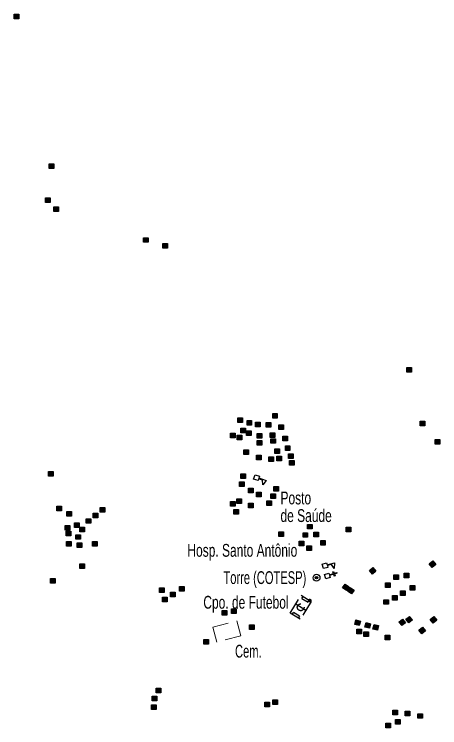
# Model space of a CAD drawing. Extents: x 220.8 to 246.7, y 7287.6 to 7315.8.
# Drawn here: x 230.652 to 233.312, y 7306.736 to 7311.191 of the extents above; entities that cross this region are included whole.
import ezdxf
from ezdxf.enums import TextEntityAlignment as Align

# ---------------------------------------------------------------- set-up
doc = ezdxf.new("R2010")
doc.units = 0
doc.header["$LTSCALE"] = 0.032
doc.header["$PDMODE"] = 32
doc.header["$PDSIZE"] = 0.016
doc.linetypes.add('MEDIUM_DASHED', pattern=[4.5, 3, -1.5])
for name, color, linetype, lineweight in [('14', 7, 'MEDIUM_DASHED', 25), ('2', 7, 'Continuous', 25), ('21', 7, 'MEDIUM_DASHED', 13), ('4', 7, 'Continuous', 25), ('47', 7, 'Continuous', 25), ('6', 7, 'Continuous', 25)]:
    doc.layers.add(name, color=color, linetype=linetype, lineweight=lineweight)
doc.layers.add('61', color=7, linetype='Continuous')

msp = doc.modelspace()

# ---------------------------------------------------------------- hatches: boundary and pattern name
at = {"layer": '2'}
for points in [[(230.6521, 7311.1911), (230.6811, 7311.1911), (230.6811, 7311.1621), (230.6521, 7311.1621)], [(230.8712, 7310.2564), (230.9002, 7310.2564), (230.9002, 7310.2274), (230.8712, 7310.2274)], [(230.8483, 7310.0453), (230.8773, 7310.0453), (230.8773, 7310.0163), (230.8483, 7310.0163)], [(230.8993, 7309.989), (230.9283, 7309.989), (230.9283, 7309.96), (230.8993, 7309.96)], [(231.4593, 7309.7959), (231.4883, 7309.7959), (231.4883, 7309.7669), (231.4593, 7309.7669)], [(231.5801, 7309.7603), (231.6091, 7309.7603), (231.6091, 7309.7313), (231.5801, 7309.7313)], [(233.1068, 7308.9847), (233.1358, 7308.9847), (233.1358, 7308.9557), (233.1068, 7308.9557)], [(232.2676, 7308.697), (232.2966, 7308.697), (232.2966, 7308.668), (232.2676, 7308.668)], [(232.0493, 7308.6713), (232.0783, 7308.6713), (232.0783, 7308.6423), (232.0493, 7308.6423)], [(232.1071, 7308.6542), (232.1361, 7308.6542), (232.1361, 7308.6252), (232.1071, 7308.6252)], [(232.1606, 7308.6435), (232.1896, 7308.6435), (232.1896, 7308.6145), (232.1606, 7308.6145)], [(232.2269, 7308.6414), (232.2559, 7308.6414), (232.2559, 7308.6124), (232.2269, 7308.6124)], [(233.1892, 7308.6494), (233.2182, 7308.6494), (233.2182, 7308.6204), (233.1892, 7308.6204)], [(232.0686, 7308.6071), (232.0976, 7308.6071), (232.0976, 7308.5781), (232.0686, 7308.5781)], [(232.3061, 7308.6264), (232.3351, 7308.6264), (232.3351, 7308.5974), (232.3061, 7308.5974)], [(232.0043, 7308.575), (232.0333, 7308.575), (232.0333, 7308.546), (232.0043, 7308.546)], [(232.045, 7308.5622), (232.074, 7308.5622), (232.074, 7308.5332), (232.045, 7308.5332)], [(232.1049, 7308.59), (232.1339, 7308.59), (232.1339, 7308.561), (232.1049, 7308.561)], [(232.1713, 7308.5729), (232.2003, 7308.5729), (232.2003, 7308.5439), (232.1713, 7308.5439)], [(232.2526, 7308.5772), (232.2816, 7308.5772), (232.2816, 7308.5482), (232.2526, 7308.5482)], [(232.3318, 7308.5558), (232.3608, 7308.5558), (232.3608, 7308.5268), (232.3318, 7308.5268)], [(232.1713, 7308.5301), (232.2003, 7308.5301), (232.2003, 7308.5011), (232.1713, 7308.5011)], [(232.2569, 7308.5408), (232.2859, 7308.5408), (232.2859, 7308.5118), (232.2569, 7308.5118)], [(233.283, 7308.5358), (233.312, 7308.5358), (233.312, 7308.5068), (233.283, 7308.5068)], [(232.0878, 7308.4702), (232.1168, 7308.4702), (232.1168, 7308.4412), (232.0878, 7308.4412)], [(232.2804, 7308.4766), (232.3094, 7308.4766), (232.3094, 7308.4476), (232.2804, 7308.4476)], [(232.3468, 7308.4958), (232.3758, 7308.4958), (232.3758, 7308.4668), (232.3468, 7308.4668)], [(232.167, 7308.4381), (232.196, 7308.4381), (232.196, 7308.4091), (232.167, 7308.4091)], [(232.2441, 7308.4274), (232.2731, 7308.4274), (232.2731, 7308.3984), (232.2441, 7308.3984)], [(232.2933, 7308.4316), (232.3223, 7308.4316), (232.3223, 7308.4026), (232.2933, 7308.4026)], [(232.3661, 7308.4466), (232.3951, 7308.4466), (232.3951, 7308.4176), (232.3661, 7308.4176)], [(232.3725, 7308.4038), (232.4015, 7308.4038), (232.4015, 7308.3748), (232.3725, 7308.3748)], [(230.8672, 7308.3354), (230.8962, 7308.3354), (230.8962, 7308.3064), (230.8672, 7308.3064)], [(232.0686, 7308.3204), (232.0976, 7308.3204), (232.0976, 7308.2914), (232.0686, 7308.2914)], [(232.06, 7308.2711), (232.089, 7308.2711), (232.089, 7308.2421), (232.06, 7308.2421)], [(232.274, 7308.2412), (232.303, 7308.2412), (232.303, 7308.2122), (232.274, 7308.2122)], [(232.1156, 7308.2326), (232.1446, 7308.2326), (232.1446, 7308.2036), (232.1156, 7308.2036)], [(232.167, 7308.2069), (232.196, 7308.2069), (232.196, 7308.1779), (232.167, 7308.1779)], [(232.2569, 7308.1962), (232.2859, 7308.1962), (232.2859, 7308.1672), (232.2569, 7308.1672)], [(232.0043, 7308.1492), (232.0333, 7308.1492), (232.0333, 7308.1202), (232.0043, 7308.1202)], [(232.0428, 7308.1641), (232.0718, 7308.1641), (232.0718, 7308.1351), (232.0428, 7308.1351)], [(232.2312, 7308.1534), (232.2602, 7308.1534), (232.2602, 7308.1244), (232.2312, 7308.1244)], [(230.9176, 7308.1184), (230.9466, 7308.1184), (230.9466, 7308.0894), (230.9176, 7308.0894)], [(231.1886, 7308.1105), (231.2176, 7308.1105), (231.2176, 7308.0815), (231.1886, 7308.0815)], [(232.1156, 7308.1385), (232.1446, 7308.1385), (232.1446, 7308.1095), (232.1156, 7308.1095)], [(230.9806, 7308.0869), (231.0096, 7308.0869), (231.0096, 7308.0579), (230.9806, 7308.0579)], [(231.1461, 7308.0759), (231.1751, 7308.0759), (231.1751, 7308.0469), (231.1461, 7308.0469)], [(232.0257, 7308.0978), (232.0547, 7308.0978), (232.0547, 7308.0688), (232.0257, 7308.0688)], [(231.102, 7308.0412), (231.131, 7308.0412), (231.131, 7308.0122), (231.102, 7308.0122)], [(230.9696, 7307.9986), (230.9986, 7307.9986), (230.9986, 7307.9696), (230.9696, 7307.9696)], [(231.0279, 7308.0144), (231.0569, 7308.0144), (231.0569, 7307.9854), (231.0279, 7307.9854)], [(231.0626, 7307.9876), (231.0916, 7307.9876), (231.0916, 7307.9586), (231.0626, 7307.9586)], [(232.4859, 7308.0058), (232.5149, 7308.0058), (232.5149, 7307.9768), (232.4859, 7307.9768)], [(232.7273, 7307.9875), (232.7563, 7307.9875), (232.7563, 7307.9585), (232.7273, 7307.9585)], [(230.9775, 7307.9624), (231.0065, 7307.9624), (231.0065, 7307.9334), (230.9775, 7307.9334)], [(231.0378, 7307.9413), (231.0668, 7307.9413), (231.0668, 7307.9123), (231.0378, 7307.9123)], [(232.3068, 7307.9599), (232.3358, 7307.9599), (232.3358, 7307.9309), (232.3068, 7307.9309)], [(232.4572, 7307.9538), (232.4862, 7307.9538), (232.4862, 7307.9248), (232.4572, 7307.9248)], [(232.5247, 7307.9568), (232.5537, 7307.9568), (232.5537, 7307.9278), (232.5247, 7307.9278)], [(230.9782, 7307.8979), (231.0072, 7307.8979), (231.0072, 7307.8689), (230.9782, 7307.8689)], [(231.046, 7307.8898), (231.075, 7307.8898), (231.075, 7307.8608), (231.046, 7307.8608)], [(231.1408, 7307.8979), (231.1698, 7307.8979), (231.1698, 7307.8689), (231.1408, 7307.8689)], [(232.4326, 7307.9016), (232.4616, 7307.9016), (232.4616, 7307.8726), (232.4326, 7307.8726)], [(232.5677, 7307.9047), (232.5967, 7307.9047), (232.5967, 7307.8757), (232.5677, 7307.8757)], [(232.4817, 7307.8709), (232.5107, 7307.8709), (232.5107, 7307.8419), (232.4817, 7307.8419)], [(231.0622, 7307.7597), (231.0912, 7307.7597), (231.0912, 7307.7307), (231.0622, 7307.7307)], [(233.2466, 7307.7595), (233.269, 7307.778), (233.2875, 7307.7557), (233.2651, 7307.7372)], [(232.8723, 7307.7179), (232.8947, 7307.7364), (232.9132, 7307.7141), (232.8908, 7307.6956)], [(230.8779, 7307.6676), (230.9069, 7307.6676), (230.9069, 7307.6386), (230.8779, 7307.6386)], [(233.0253, 7307.6904), (233.0543, 7307.6904), (233.0543, 7307.6614), (233.0253, 7307.6614)], [(233.0904, 7307.7), (233.1194, 7307.7), (233.1194, 7307.671), (233.0904, 7307.671)], [(231.6853, 7307.6178), (231.7143, 7307.6178), (231.7143, 7307.5888), (231.6853, 7307.5888)], [(232.7216, 7307.6329), (232.7453, 7307.6161), (232.7284, 7307.5925), (232.7048, 7307.6093)], [(232.9736, 7307.6406), (233.0026, 7307.6406), (233.0026, 7307.6116), (232.9736, 7307.6116)], [(233.1268, 7307.6234), (233.1558, 7307.6234), (233.1558, 7307.5944), (233.1268, 7307.5944)], [(231.5601, 7307.6095), (231.5891, 7307.6095), (231.5891, 7307.5805), (231.5601, 7307.5805)], [(231.6296, 7307.5817), (231.6586, 7307.5817), (231.6586, 7307.5527), (231.6296, 7307.5527)], [(232.7526, 7307.6115), (232.7763, 7307.5947), (232.7594, 7307.5711), (232.7358, 7307.5879)], [(233.0674, 7307.5909), (233.0964, 7307.5909), (233.0964, 7307.5619), (233.0674, 7307.5619)], [(231.5796, 7307.5511), (231.6086, 7307.5511), (231.6086, 7307.5221), (231.5796, 7307.5221)], [(232.9621, 7307.5353), (232.9911, 7307.5353), (232.9911, 7307.5063), (232.9621, 7307.5063)], [(233.0176, 7307.5621), (233.0466, 7307.5621), (233.0466, 7307.5331), (233.0176, 7307.5331)], [(231.9523, 7307.4677), (231.9813, 7307.4677), (231.9813, 7307.4387), (231.9523, 7307.4387)], [(232.0107, 7307.4788), (232.0397, 7307.4788), (232.0397, 7307.4498), (232.0107, 7307.4498)], [(232.788, 7307.409), (232.8161, 7307.402), (232.8092, 7307.3739), (232.781, 7307.3808)], [(232.8517, 7307.3921), (232.8798, 7307.3851), (232.8729, 7307.357), (232.8447, 7307.3639)], [(233.056, 7307.3954), (233.0784, 7307.4139), (233.0969, 7307.3916), (233.0745, 7307.3731)], [(233.101, 7307.4127), (233.1234, 7307.4312), (233.1419, 7307.4089), (233.1195, 7307.3904)], [(233.2531, 7307.4109), (233.2755, 7307.4294), (233.294, 7307.4071), (233.2716, 7307.3886)], [(232.1219, 7307.3787), (232.1509, 7307.3787), (232.1509, 7307.3497), (232.1219, 7307.3497)], [(232.7933, 7307.3518), (232.8223, 7307.3518), (232.8223, 7307.3228), (232.7933, 7307.3228)], [(232.901, 7307.3804), (232.9291, 7307.3734), (232.9222, 7307.3453), (232.894, 7307.3522)], [(233.1817, 7307.3443), (233.2041, 7307.3628), (233.2226, 7307.3405), (233.2002, 7307.322)], [(232.8384, 7307.3345), (232.8674, 7307.3345), (232.8674, 7307.3055), (232.8384, 7307.3055)], [(232.9701, 7307.3137), (232.9991, 7307.3137), (232.9991, 7307.2847), (232.9701, 7307.2847)], [(231.8382, 7307.2869), (231.8672, 7307.2869), (231.8672, 7307.2579), (231.8382, 7307.2579)], [(231.5386, 7306.983), (231.5676, 7306.983), (231.5676, 7306.954), (231.5386, 7306.954)], [(231.514, 7306.9324), (231.543, 7306.9324), (231.543, 7306.9034), (231.514, 7306.9034)], [(232.2679, 7306.9091), (232.2969, 7306.9091), (232.2969, 7306.8801), (232.2679, 7306.8801)], [(231.511, 7306.8788), (231.54, 7306.8788), (231.54, 7306.8498), (231.511, 7306.8498)], [(232.2185, 7306.8957), (232.2475, 7306.8957), (232.2475, 7306.8667), (232.2185, 7306.8667)], [(233.0192, 7306.8444), (233.0482, 7306.8444), (233.0482, 7306.8154), (233.0192, 7306.8154)], [(233.0968, 7306.8381), (233.1258, 7306.8381), (233.1258, 7306.8091), (233.0968, 7306.8091)], [(233.1745, 7306.8235), (233.2035, 7306.8235), (233.2035, 7306.7945), (233.1745, 7306.7945)], [(233.036, 7306.7878), (233.065, 7306.7878), (233.065, 7306.7588), (233.036, 7306.7588)], [(232.9751, 7306.7647), (233.0041, 7306.7647), (233.0041, 7306.7357), (232.9751, 7306.7357)]]:
    msp.add_hatch(color=256, dxfattribs=at).paths.add_polyline_path(points)

# ---------------------------------------------------------------- linework, layer by layer
at = {"layer": '14'}
for p, q in [((232.4507, 7307.543), (232.4582, 7307.5552)), ((232.4507, 7307.543), (232.4886, 7307.5198)), ((232.4597, 7307.5542), (232.4597, 7307.5547)), ((232.4961, 7307.532), (232.4886, 7307.5198)), ((232.4993, 7307.5301), (232.4992, 7307.5301)), ((232.474, 7307.4687), (232.4117, 7307.5068)), ((232.3896, 7307.4434), (232.3971, 7307.4556)), ((232.435, 7307.4324), (232.3971, 7307.4556)), ((232.435, 7307.4324), (232.4276, 7307.4202))]:
    msp.add_line(p, q, dxfattribs=at)
msp.add_lwpolyline([(232.446, 7307.5627), (232.5083, 7307.5246), (232.4398, 7307.4127), (232.3774, 7307.4509)], close=True, dxfattribs=at)
msp.add_circle((232.4428, 7307.4877), 0.0212, dxfattribs=at)
msp.add_point((232.499, 7307.5303), dxfattribs=at)
at = {"layer": '2'}
for points in [[(230.6521, 7311.1911), (230.6811, 7311.1911), (230.6811, 7311.1621), (230.6521, 7311.1621)], [(230.8712, 7310.2564), (230.9002, 7310.2564), (230.9002, 7310.2274), (230.8712, 7310.2274)], [(230.8483, 7310.0453), (230.8773, 7310.0453), (230.8773, 7310.0163), (230.8483, 7310.0163)], [(230.8993, 7309.989), (230.9283, 7309.989), (230.9283, 7309.96), (230.8993, 7309.96)], [(231.4593, 7309.7959), (231.4883, 7309.7959), (231.4883, 7309.7669), (231.4593, 7309.7669)], [(231.5801, 7309.7603), (231.6091, 7309.7603), (231.6091, 7309.7313), (231.5801, 7309.7313)], [(233.1068, 7308.9847), (233.1358, 7308.9847), (233.1358, 7308.9557), (233.1068, 7308.9557)], [(232.2676, 7308.697), (232.2966, 7308.697), (232.2966, 7308.668), (232.2676, 7308.668)], [(232.0493, 7308.6713), (232.0783, 7308.6713), (232.0783, 7308.6423), (232.0493, 7308.6423)], [(232.1071, 7308.6542), (232.1361, 7308.6542), (232.1361, 7308.6252), (232.1071, 7308.6252)], [(232.1606, 7308.6435), (232.1896, 7308.6435), (232.1896, 7308.6145), (232.1606, 7308.6145)], [(232.2269, 7308.6414), (232.2559, 7308.6414), (232.2559, 7308.6124), (232.2269, 7308.6124)], [(233.1892, 7308.6494), (233.2182, 7308.6494), (233.2182, 7308.6204), (233.1892, 7308.6204)], [(232.0686, 7308.6071), (232.0976, 7308.6071), (232.0976, 7308.5781), (232.0686, 7308.5781)], [(232.3061, 7308.6264), (232.3351, 7308.6264), (232.3351, 7308.5974), (232.3061, 7308.5974)], [(232.0043, 7308.575), (232.0333, 7308.575), (232.0333, 7308.546), (232.0043, 7308.546)], [(232.045, 7308.5622), (232.074, 7308.5622), (232.074, 7308.5332), (232.045, 7308.5332)], [(232.1049, 7308.59), (232.1339, 7308.59), (232.1339, 7308.561), (232.1049, 7308.561)], [(232.1713, 7308.5729), (232.2003, 7308.5729), (232.2003, 7308.5439), (232.1713, 7308.5439)], [(232.2526, 7308.5772), (232.2816, 7308.5772), (232.2816, 7308.5482), (232.2526, 7308.5482)], [(232.3318, 7308.5558), (232.3608, 7308.5558), (232.3608, 7308.5268), (232.3318, 7308.5268)], [(232.1713, 7308.5301), (232.2003, 7308.5301), (232.2003, 7308.5011), (232.1713, 7308.5011)], [(232.2569, 7308.5408), (232.2859, 7308.5408), (232.2859, 7308.5118), (232.2569, 7308.5118)], [(233.283, 7308.5358), (233.312, 7308.5358), (233.312, 7308.5068), (233.283, 7308.5068)], [(232.0878, 7308.4702), (232.1168, 7308.4702), (232.1168, 7308.4412), (232.0878, 7308.4412)], [(232.2804, 7308.4766), (232.3094, 7308.4766), (232.3094, 7308.4476), (232.2804, 7308.4476)], [(232.3468, 7308.4958), (232.3758, 7308.4958), (232.3758, 7308.4668), (232.3468, 7308.4668)], [(232.167, 7308.4381), (232.196, 7308.4381), (232.196, 7308.4091), (232.167, 7308.4091)], [(232.2441, 7308.4274), (232.2731, 7308.4274), (232.2731, 7308.3984), (232.2441, 7308.3984)], [(232.2933, 7308.4316), (232.3223, 7308.4316), (232.3223, 7308.4026), (232.2933, 7308.4026)], [(232.3661, 7308.4466), (232.3951, 7308.4466), (232.3951, 7308.4176), (232.3661, 7308.4176)], [(232.3725, 7308.4038), (232.4015, 7308.4038), (232.4015, 7308.3748), (232.3725, 7308.3748)], [(230.8672, 7308.3354), (230.8962, 7308.3354), (230.8962, 7308.3064), (230.8672, 7308.3064)], [(232.0686, 7308.3204), (232.0976, 7308.3204), (232.0976, 7308.2914), (232.0686, 7308.2914)], [(232.06, 7308.2711), (232.089, 7308.2711), (232.089, 7308.2421), (232.06, 7308.2421)], [(232.274, 7308.2412), (232.303, 7308.2412), (232.303, 7308.2122), (232.274, 7308.2122)], [(232.1156, 7308.2326), (232.1446, 7308.2326), (232.1446, 7308.2036), (232.1156, 7308.2036)], [(232.167, 7308.2069), (232.196, 7308.2069), (232.196, 7308.1779), (232.167, 7308.1779)], [(232.2569, 7308.1962), (232.2859, 7308.1962), (232.2859, 7308.1672), (232.2569, 7308.1672)], [(232.0043, 7308.1492), (232.0333, 7308.1492), (232.0333, 7308.1202), (232.0043, 7308.1202)], [(232.0428, 7308.1641), (232.0718, 7308.1641), (232.0718, 7308.1351), (232.0428, 7308.1351)], [(232.2312, 7308.1534), (232.2602, 7308.1534), (232.2602, 7308.1244), (232.2312, 7308.1244)], [(230.9176, 7308.1184), (230.9466, 7308.1184), (230.9466, 7308.0894), (230.9176, 7308.0894)], [(231.1886, 7308.1105), (231.2176, 7308.1105), (231.2176, 7308.0815), (231.1886, 7308.0815)], [(232.1156, 7308.1385), (232.1446, 7308.1385), (232.1446, 7308.1095), (232.1156, 7308.1095)], [(230.9806, 7308.0869), (231.0096, 7308.0869), (231.0096, 7308.0579), (230.9806, 7308.0579)], [(231.1461, 7308.0759), (231.1751, 7308.0759), (231.1751, 7308.0469), (231.1461, 7308.0469)], [(232.0257, 7308.0978), (232.0547, 7308.0978), (232.0547, 7308.0688), (232.0257, 7308.0688)], [(231.102, 7308.0412), (231.131, 7308.0412), (231.131, 7308.0122), (231.102, 7308.0122)], [(230.9696, 7307.9986), (230.9986, 7307.9986), (230.9986, 7307.9696), (230.9696, 7307.9696)], [(231.0279, 7308.0144), (231.0569, 7308.0144), (231.0569, 7307.9854), (231.0279, 7307.9854)], [(231.0626, 7307.9876), (231.0916, 7307.9876), (231.0916, 7307.9586), (231.0626, 7307.9586)], [(232.4859, 7308.0058), (232.5149, 7308.0058), (232.5149, 7307.9768), (232.4859, 7307.9768)], [(232.7273, 7307.9875), (232.7563, 7307.9875), (232.7563, 7307.9585), (232.7273, 7307.9585)], [(230.9775, 7307.9624), (231.0065, 7307.9624), (231.0065, 7307.9334), (230.9775, 7307.9334)], [(231.0378, 7307.9413), (231.0668, 7307.9413), (231.0668, 7307.9123), (231.0378, 7307.9123)], [(232.3068, 7307.9599), (232.3358, 7307.9599), (232.3358, 7307.9309), (232.3068, 7307.9309)], [(232.4572, 7307.9538), (232.4862, 7307.9538), (232.4862, 7307.9248), (232.4572, 7307.9248)], [(232.5247, 7307.9568), (232.5537, 7307.9568), (232.5537, 7307.9278), (232.5247, 7307.9278)], [(230.9782, 7307.8979), (231.0072, 7307.8979), (231.0072, 7307.8689), (230.9782, 7307.8689)], [(231.046, 7307.8898), (231.075, 7307.8898), (231.075, 7307.8608), (231.046, 7307.8608)], [(231.1408, 7307.8979), (231.1698, 7307.8979), (231.1698, 7307.8689), (231.1408, 7307.8689)], [(232.4326, 7307.9016), (232.4616, 7307.9016), (232.4616, 7307.8726), (232.4326, 7307.8726)], [(232.5677, 7307.9047), (232.5967, 7307.9047), (232.5967, 7307.8757), (232.5677, 7307.8757)], [(232.4817, 7307.8709), (232.5107, 7307.8709), (232.5107, 7307.8419), (232.4817, 7307.8419)], [(231.0622, 7307.7597), (231.0912, 7307.7597), (231.0912, 7307.7307), (231.0622, 7307.7307)], [(233.2466, 7307.7595), (233.269, 7307.778), (233.2875, 7307.7557), (233.2651, 7307.7372)], [(232.8723, 7307.7179), (232.8947, 7307.7364), (232.9132, 7307.7141), (232.8908, 7307.6956)], [(230.8779, 7307.6676), (230.9069, 7307.6676), (230.9069, 7307.6386), (230.8779, 7307.6386)], [(233.0253, 7307.6904), (233.0543, 7307.6904), (233.0543, 7307.6614), (233.0253, 7307.6614)], [(233.0904, 7307.7), (233.1194, 7307.7), (233.1194, 7307.671), (233.0904, 7307.671)], [(231.6853, 7307.6178), (231.7143, 7307.6178), (231.7143, 7307.5888), (231.6853, 7307.5888)], [(232.7216, 7307.6329), (232.7453, 7307.6161), (232.7284, 7307.5925), (232.7048, 7307.6093)], [(232.9736, 7307.6406), (233.0026, 7307.6406), (233.0026, 7307.6116), (232.9736, 7307.6116)], [(233.1268, 7307.6234), (233.1558, 7307.6234), (233.1558, 7307.5944), (233.1268, 7307.5944)], [(231.5601, 7307.6095), (231.5891, 7307.6095), (231.5891, 7307.5805), (231.5601, 7307.5805)], [(231.6296, 7307.5817), (231.6586, 7307.5817), (231.6586, 7307.5527), (231.6296, 7307.5527)], [(232.7526, 7307.6115), (232.7763, 7307.5947), (232.7594, 7307.5711), (232.7358, 7307.5879)], [(233.0674, 7307.5909), (233.0964, 7307.5909), (233.0964, 7307.5619), (233.0674, 7307.5619)], [(231.5796, 7307.5511), (231.6086, 7307.5511), (231.6086, 7307.5221), (231.5796, 7307.5221)], [(232.9621, 7307.5353), (232.9911, 7307.5353), (232.9911, 7307.5063), (232.9621, 7307.5063)], [(233.0176, 7307.5621), (233.0466, 7307.5621), (233.0466, 7307.5331), (233.0176, 7307.5331)], [(231.9523, 7307.4677), (231.9813, 7307.4677), (231.9813, 7307.4387), (231.9523, 7307.4387)], [(232.0107, 7307.4788), (232.0397, 7307.4788), (232.0397, 7307.4498), (232.0107, 7307.4498)], [(232.788, 7307.409), (232.8161, 7307.402), (232.8092, 7307.3739), (232.781, 7307.3808)], [(232.8517, 7307.3921), (232.8798, 7307.3851), (232.8729, 7307.357), (232.8447, 7307.3639)], [(233.056, 7307.3954), (233.0784, 7307.4139), (233.0969, 7307.3916), (233.0745, 7307.3731)], [(233.101, 7307.4127), (233.1234, 7307.4312), (233.1419, 7307.4089), (233.1195, 7307.3904)], [(233.2531, 7307.4109), (233.2755, 7307.4294), (233.294, 7307.4071), (233.2716, 7307.3886)], [(232.1219, 7307.3787), (232.1509, 7307.3787), (232.1509, 7307.3497), (232.1219, 7307.3497)], [(232.7933, 7307.3518), (232.8223, 7307.3518), (232.8223, 7307.3228), (232.7933, 7307.3228)], [(232.901, 7307.3804), (232.9291, 7307.3734), (232.9222, 7307.3453), (232.894, 7307.3522)], [(233.1817, 7307.3443), (233.2041, 7307.3628), (233.2226, 7307.3405), (233.2002, 7307.322)], [(232.8384, 7307.3345), (232.8674, 7307.3345), (232.8674, 7307.3055), (232.8384, 7307.3055)], [(232.9701, 7307.3137), (232.9991, 7307.3137), (232.9991, 7307.2847), (232.9701, 7307.2847)], [(231.8382, 7307.2869), (231.8672, 7307.2869), (231.8672, 7307.2579), (231.8382, 7307.2579)], [(231.5386, 7306.983), (231.5676, 7306.983), (231.5676, 7306.954), (231.5386, 7306.954)], [(231.514, 7306.9324), (231.543, 7306.9324), (231.543, 7306.9034), (231.514, 7306.9034)], [(232.2679, 7306.9091), (232.2969, 7306.9091), (232.2969, 7306.8801), (232.2679, 7306.8801)], [(231.511, 7306.8788), (231.54, 7306.8788), (231.54, 7306.8498), (231.511, 7306.8498)], [(232.2185, 7306.8957), (232.2475, 7306.8957), (232.2475, 7306.8667), (232.2185, 7306.8667)], [(233.0192, 7306.8444), (233.0482, 7306.8444), (233.0482, 7306.8154), (233.0192, 7306.8154)], [(233.0968, 7306.8381), (233.1258, 7306.8381), (233.1258, 7306.8091), (233.0968, 7306.8091)], [(233.1745, 7306.8235), (233.2035, 7306.8235), (233.2035, 7306.7945), (233.1745, 7306.7945)], [(233.036, 7306.7878), (233.065, 7306.7878), (233.065, 7306.7588), (233.036, 7306.7588)], [(232.9751, 7306.7647), (233.0041, 7306.7647), (233.0041, 7306.7357), (232.9751, 7306.7357)]]:
    msp.add_lwpolyline(points, close=True, dxfattribs=at)
at = {"layer": '21'}
msp.add_lwpolyline([(231.8934, 7307.3633), (232.0426, 7307.4038), (232.068, 7307.3102), (231.9188, 7307.2697)], close=True, dxfattribs=at)
at = {"layer": '4'}
for points in [[(232.1796, 7308.2909), (232.1759, 7308.2794), (232.1483, 7308.2885), (232.1574, 7308.316), (232.185, 7308.3069), (232.1812, 7308.2956)], [(232.1812, 7308.2956), (232.2271, 7308.2803), (232.2054, 7308.2518), (232.2044, 7308.2827), (232.1796, 7308.2909)], [(232.6093, 7307.7483), (232.6124, 7307.7366), (232.5843, 7307.7293), (232.577, 7307.7574), (232.6051, 7307.7647), (232.6081, 7307.7531)], [(232.6081, 7307.7531), (232.6549, 7307.7652), (232.6522, 7307.7295), (232.6346, 7307.7549), (232.6093, 7307.7483)]]:
    msp.add_lwpolyline(points, dxfattribs=at)
at = {"layer": '47'}
msp.add_circle((232.5417, 7307.6727), 0.0215, dxfattribs=at)
msp.add_point((232.5419, 7307.6726), dxfattribs=at)
at = {"layer": '6'}
for points in [[(232.6219, 7307.6902), (232.6478, 7307.6984), (232.6441, 7307.7099), (232.6488, 7307.7114), (232.6524, 7307.6999), (232.6681, 7307.7048), (232.6695, 7307.7003), (232.6539, 7307.6953), (232.6575, 7307.6838), (232.6529, 7307.6823), (232.6492, 7307.6938), (232.6234, 7307.6856)], [(232.6234, 7307.6856), (232.627, 7307.6741), (232.5994, 7307.6653), (232.5906, 7307.693), (232.6183, 7307.7018), (232.6219, 7307.6902)]]:
    msp.add_lwpolyline(points, dxfattribs=at)

# ---------------------------------------------------------------- texts
at = {"layer": '61'}
for s, width, p in [('Posto', 0.7, (232.3165, 7308.1304)), ('de Saúde', 0.7, (232.3165, 7308.0204)), ('Cem.', 0.65, (232.0324, 7307.1737))]:
    msp.add_text(s, height=0.08, dxfattribs=dict(at, width=width)).set_placement(p)
for s, width, p in [('Hosp. Santo Antônio', 0.7, (232.4214, 7307.8035)), ('Torre (COTESP)', 0.65, (232.4776, 7307.6331)), ('Cpo. de Futebol', 0.7, (232.367, 7307.4791))]:
    msp.add_text(s, height=0.08, dxfattribs=dict(at, width=width)).set_placement(p, align=Align.RIGHT)

doc.saveas('drawing.dxf')
